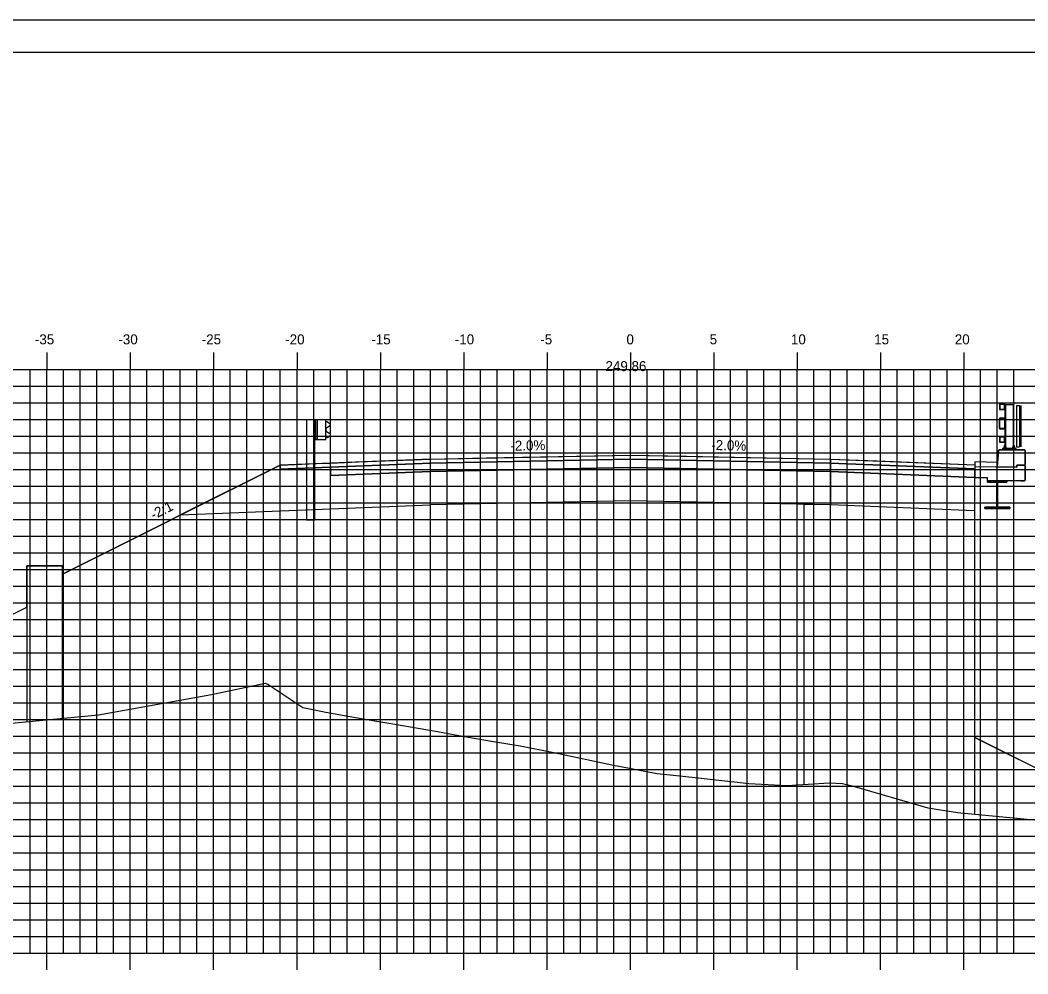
# Model space of a CAD drawing. Extents: x -22 to 1480, y -1511 to 8.
# Drawn here: x 816.8 to 877.3, y -1458.6 to -1401.4 of the extents above; entities that cross this region are included whole.
import ezdxf

# ---------------------------------------------------------------- set-up
doc = ezdxf.new("R2010")
doc.units = 0
for name, color, linetype in [('ANNOTATION', 7, 'Continuous'), ('BORDER', 7, 'Continuous'), ('D_Bridge_Deck', 7, 'Continuous'), ('D_Bridge_Railing', 7, 'Continuous'), ('D_Bridge_Superstructure', 7, 'Continuous'), ('D_Bridge_Superstructure_Slab', 7, 'Continuous'), ('D_Bridge_Wingwall', 7, 'Continuous'), ('D_Guardrail_Beam_Lt', 7, 'Continuous'), ('D_Roadway_Centerline', 7, 'Continuous'), ('D_Roadway_Centerline_Text', 7, 'Continuous'), ('D_Roadway_Edge_Shoulder', 7, 'Continuous'), ('D_Roadway_Edge_TW', 7, 'Continuous'), ('D_Roadway_Pavement', 7, 'Continuous'), ('D_Roadway_SlopeLines', 7, 'Continuous'), ('D_Roadway_SubGrade', 7, 'Continuous'), ('H_V ANNOTATION', 7, 'Continuous'), ('MAJOR', 7, 'Continuous'), ('MINOR', 7, 'Continuous'), ('PLOT BOUNDARY', 7, 'Continuous'), ('S_Roadway_Centerline', 7, 'Continuous')]:
    doc.layers.add(name, color=color, linetype=linetype)

msp = doc.modelspace()

# ---------------------------------------------------------------- linework, layer by layer
at = {"layer": 'BORDER'}
msp.add_line((938.426, -1403.331), (778.426, -1403.331), dxfattribs=at)
at = {"layer": 'D_Bridge_Deck'}
for p, q in [((876.593, -1428.203), (876.593, -1428.078)), ((876.593, -1428.078), (877.051, -1428.078))]:
    msp.add_line(p, q, dxfattribs=at)
for points in [[(877.051, -1428.078), (877.093, -1428.036), (877.093, -1427.2), (877.051, -1427.159), (875.551, -1427.159), (875.506, -1427.2), (875.426, -1428.18)], [(876.801, -1429.013), (876.092, -1429.013)]]:
    msp.add_lwpolyline(points, dxfattribs=at)
at = {"layer": 'D_Bridge_Railing'}
for p, q in [((875.551, -1424.45), (875.551, -1424.7)), ((875.572, -1424.45), (875.572, -1424.7)), ((875.843, -1424.409), (875.593, -1424.409)), ((875.843, -1424.43), (875.593, -1424.43)), ((875.863, -1424.7), (875.863, -1424.45)), ((875.884, -1424.7), (875.884, -1424.45)), ((875.922, -1424.45), (875.922, -1426.982)), ((876.378, -1424.45), (876.378, -1426.982)), ((876.582, -1424.492), (876.582, -1426.983)), ((876.582, -1424.492), (876.749, -1424.492)), ((876.749, -1424.492), (876.749, -1426.983)), ((875.593, -1424.721), (875.843, -1424.721)), ((875.593, -1424.742), (875.843, -1424.742)), ((875.551, -1425.857), (875.551, -1425.294)), ((875.577, -1425.857), (875.577, -1425.294)), ((875.603, -1425.242), (875.832, -1425.242)), ((875.603, -1425.268), (875.832, -1425.268)), ((875.858, -1425.294), (875.858, -1425.857)), ((875.884, -1425.294), (875.884, -1425.857)), ((875.832, -1425.883), (875.603, -1425.883)), ((875.832, -1425.909), (875.603, -1425.909)), ((875.551, -1426.409), (875.551, -1426.659)), ((875.572, -1426.409), (875.572, -1426.659)), ((875.843, -1426.367), (875.593, -1426.367)), ((875.843, -1426.388), (875.593, -1426.388)), ((875.593, -1426.68), (875.843, -1426.68)), ((875.593, -1426.7), (875.843, -1426.7)), ((875.921, -1426.909), (875.848, -1426.909)), ((875.921, -1426.917), (875.848, -1426.917)), ((875.921, -1426.925), (875.848, -1426.925)), ((875.921, -1426.933), (875.848, -1426.933)), ((875.863, -1426.659), (875.863, -1426.409)), ((875.903, -1426.913), (875.866, -1426.913)), ((875.903, -1426.921), (875.866, -1426.921)), ((875.903, -1426.929), (875.866, -1426.929)), ((875.903, -1426.938), (875.866, -1426.938)), ((875.884, -1426.659), (875.884, -1426.409)), ((876.452, -1426.909), (876.379, -1426.909)), ((876.452, -1426.917), (876.379, -1426.917)), ((876.452, -1426.925), (876.379, -1426.925)), ((876.452, -1426.933), (876.379, -1426.933)), ((876.434, -1426.913), (876.397, -1426.913)), ((876.434, -1426.921), (876.397, -1426.921)), ((876.434, -1426.929), (876.397, -1426.929)), ((876.434, -1426.938), (876.397, -1426.938)), ((875.921, -1426.942), (875.848, -1426.942)), ((875.921, -1426.95), (875.848, -1426.95)), ((875.921, -1426.958), (875.848, -1426.958)), ((875.921, -1426.967), (875.848, -1426.967)), ((875.921, -1426.975), (875.848, -1426.975)), ((875.85, -1426.99), (875.85, -1427.046)), ((875.903, -1426.946), (875.866, -1426.946)), ((875.903, -1426.954), (875.866, -1426.954)), ((875.903, -1426.962), (875.866, -1426.962)), ((875.903, -1426.971), (875.866, -1426.971)), ((875.903, -1426.979), (875.866, -1426.979)), ((875.919, -1426.99), (875.919, -1427.046)), ((876.452, -1426.942), (876.379, -1426.942)), ((876.452, -1426.95), (876.379, -1426.95)), ((876.452, -1426.958), (876.379, -1426.958)), ((876.452, -1426.967), (876.379, -1426.967)), ((876.452, -1426.975), (876.379, -1426.975)), ((876.381, -1426.99), (876.381, -1427.046)), ((876.434, -1426.946), (876.397, -1426.946)), ((876.434, -1426.954), (876.397, -1426.954)), ((876.434, -1426.962), (876.397, -1426.962)), ((876.434, -1426.971), (876.397, -1426.971)), ((876.434, -1426.979), (876.397, -1426.979)), ((876.45, -1426.99), (876.45, -1427.046)), ((876.582, -1426.983), (876.749, -1426.983))]:
    msp.add_line(p, q, dxfattribs=at)
for points in [[(876.416, -1426.9), (876.416, -1424.45), (875.884, -1424.45), (875.884, -1426.9)], [(876.832, -1424.492), (876.832, -1426.983)], [(875.921, -1426.982), (875.921, -1426.909), (875.912, -1426.9), (875.856, -1426.9), (875.848, -1426.909), (875.848, -1426.982)], [(876.452, -1426.982), (876.452, -1426.909), (876.444, -1426.9), (876.387, -1426.9), (876.379, -1426.909), (876.379, -1426.982)]]:
    msp.add_lwpolyline(points, dxfattribs=at)
for points in [[(876.56, -1427.067), (875.74, -1427.067), (875.74, -1427.149), (876.56, -1427.149)], [(876.56, -1427.149), (875.74, -1427.149), (875.74, -1427.159), (876.56, -1427.159)], [(875.957, -1427.067), (875.811, -1427.067), (875.811, -1427.054), (875.957, -1427.054)], [(875.953, -1426.99), (875.939, -1426.982), (875.829, -1426.982), (875.815, -1426.99), (875.815, -1427.046), (875.829, -1427.054), (875.939, -1427.054), (875.953, -1427.046)], [(876.488, -1427.067), (876.343, -1427.067), (876.343, -1427.054), (876.488, -1427.054)], [(876.484, -1426.99), (876.471, -1426.982), (876.36, -1426.982), (876.347, -1426.99), (876.347, -1427.046), (876.36, -1427.054), (876.471, -1427.054), (876.484, -1427.046)]]:
    msp.add_lwpolyline(points, close=True, dxfattribs=at)
for centre, radius, start, end in [((875.593, -1424.45), 0.0417, 90, 180), ((875.593, -1424.45), 0.0208, 90, 180), ((875.843, -1424.45), 0.0417, 360, 90), ((875.843, -1424.45), 0.0208, 360, 90), ((875.593, -1424.7), 0.0417, 180, 270), ((875.593, -1424.7), 0.0208, 180, 270), ((875.843, -1424.7), 0.0417, 270, 0), ((875.843, -1424.7), 0.0208, 270, 0), ((875.603, -1425.294), 0.052, 90, 180), ((875.603, -1425.294), 0.026, 90, 180), ((875.832, -1425.294), 0.052, 360, 90), ((875.832, -1425.294), 0.026, 360, 90), ((875.603, -1425.857), 0.052, 180, 270), ((875.603, -1425.857), 0.026, 180, 270), ((875.832, -1425.857), 0.052, 270, 0), ((875.832, -1425.857), 0.026, 270, 0), ((875.593, -1426.409), 0.0417, 90, 180), ((875.593, -1426.659), 0.0417, 180, 270), ((875.593, -1426.409), 0.0208, 90, 180), ((875.593, -1426.659), 0.0208, 180, 270), ((875.843, -1426.409), 0.0417, 360, 90), ((875.843, -1426.409), 0.0208, 360, 90), ((875.843, -1426.659), 0.0417, 270, 0), ((875.843, -1426.659), 0.0208, 270, 0), ((875.833, -1427.015), 0.0302, 55.4339, 120), ((875.833, -1427.021), 0.0302, 240, 304.5661), ((875.884, -1427.099), 0.114, 72.41205, 107.58795), ((875.884, -1426.937), 0.114, 252.41205, 287.58795), ((875.936, -1427.015), 0.0302, 60, 124.5661), ((875.936, -1427.021), 0.0302, 235.4339, 300), ((876.364, -1427.015), 0.0302, 55.4339, 120), ((876.364, -1427.021), 0.0302, 240, 304.5661), ((876.416, -1427.099), 0.114, 72.41205, 107.58795), ((876.416, -1426.937), 0.114, 252.41205, 287.58795), ((876.467, -1427.015), 0.0302, 60, 124.5661), ((876.467, -1427.021), 0.0302, 235.4339, 300)]:
    msp.add_arc(centre, radius, start, end, dxfattribs=at)
at = {"layer": 'D_Bridge_Superstructure'}
for p, q in [((876.009, -1429.013), (874.842, -1429.013)), ((874.842, -1429.013), (874.842, -1429.096)), ((875.447, -1429.096), (875.405, -1429.096)), ((875.447, -1429.096), (875.405, -1429.096)), ((875.447, -1429.096), (876.009, -1429.096)), ((876.009, -1429.096), (876.009, -1429.013)), ((875.405, -1430.596), (874.676, -1430.596)), ((874.676, -1430.596), (874.676, -1430.68)), ((875.405, -1430.596), (874.676, -1430.596)), ((875.447, -1430.596), (875.405, -1430.596)), ((875.447, -1430.596), (875.405, -1430.596))]:
    msp.add_line(p, q, dxfattribs=at)
for points in [[(874.842, -1429.013), (876.009, -1429.013), (876.009, -1429.096), (874.842, -1429.096)], [(875.405, -1429.096), (875.447, -1429.096), (875.447, -1430.596), (875.405, -1430.596)], [(874.676, -1430.596), (876.176, -1430.596), (876.176, -1430.68), (874.676, -1430.68)]]:
    msp.add_lwpolyline(points, close=True, dxfattribs=at)
for points in [[(875.447, -1429.096), (876.009, -1429.096), (876.009, -1429.013), (874.842, -1429.013), (874.842, -1429.096), (875.405, -1429.096), (875.447, -1429.096)], [(874.842, -1429.096), (875.405, -1429.096), (875.447, -1429.096)], [(875.405, -1429.096), (875.405, -1430.596), (875.447, -1430.596), (875.447, -1429.096)], [(875.405, -1429.096), (875.405, -1430.596), (875.447, -1430.596), (875.447, -1429.096)], [(874.676, -1430.596), (874.676, -1430.68), (876.176, -1430.68), (876.176, -1430.596), (875.447, -1430.596)], [(874.676, -1430.68), (876.176, -1430.68), (876.176, -1430.596), (875.447, -1430.596)]]:
    msp.add_lwpolyline(points, dxfattribs=at)
at = {"layer": 'D_Bridge_Superstructure_Slab'}
msp.add_line((874.083, -1427.882), (874.083, -1428.805), dxfattribs=at)
msp.add_lwpolyline([(875.426, -1428.18), (875.506, -1427.2), (875.551, -1427.159), (877.051, -1427.159), (877.093, -1427.2), (877.093, -1428.036), (877.051, -1428.078), (876.593, -1428.078), (876.593, -1428.203)], close=True, dxfattribs=at)
for points in [[(874.083, -1428.153), (875.426, -1428.18), (875.448, -1427.909), (874.083, -1427.882)], [(874.083, -1428.153), (876.593, -1428.203), (876.593, -1428.078), (877.051, -1428.078), (877.093, -1428.12), (877.093, -1428.971), (877.051, -1429.013), (876.843, -1429.013), (876.843, -1428.971), (876.801, -1429.013), (874.842, -1429.013), (874.842, -1428.835), (874.083, -1428.819)], [(876.843, -1429.013), (877.051, -1429.013), (877.093, -1428.971), (877.093, -1428.12), (877.051, -1428.078)], [(874.083, -1428.153), (876.593, -1428.203)], [(874.083, -1428.819), (874.842, -1428.835)], [(876.092, -1429.013), (874.842, -1429.013), (874.842, -1428.835)], [(876.843, -1429.013), (876.843, -1428.971), (876.801, -1429.013)], [(876.843, -1429.013), (876.843, -1428.971), (876.801, -1429.013)]]:
    msp.add_lwpolyline(points, dxfattribs=at)
at = {"layer": 'D_Bridge_Wingwall'}
for points in [[(874.083, -1448.999), (874.083, -1430.805), (865.426, -1430.459), (863.817, -1430.427), (863.817, -1447.222)], [(819.36, -1443.26), (819.36, -1434.102), (817.217, -1434.102), (817.217, -1434.102), (817.217, -1443.464)]]:
    msp.add_lwpolyline(points, dxfattribs=at)
at = {"layer": 'D_Guardrail_Beam_Lt'}
for p, q in [((833.997, -1425.365), (833.997, -1431.365)), ((834.468, -1425.365), (833.997, -1425.365)), ((835.155, -1425.365), (834.468, -1425.365)), ((834.468, -1425.365), (834.468, -1426.532)), ((834.53, -1425.365), (834.53, -1426.532)), ((834.634, -1425.365), (834.634, -1426.532)), ((835.155, -1426.532), (835.155, -1425.365)), ((835.155, -1425.449), (835.229, -1425.463)), ((835.389, -1425.713), (835.193, -1425.849)), ((835.245, -1425.47), (835.389, -1425.57)), ((835.16, -1425.914), (835.16, -1425.984)), ((835.193, -1426.048), (835.389, -1426.184)), ((835.389, -1426.327), (835.245, -1426.427)), ((834.468, -1426.532), (835.155, -1426.532)), ((834.489, -1431.365), (834.489, -1426.532)), ((835.229, -1426.434), (835.155, -1426.449)), ((834.489, -1431.365), (833.997, -1431.365))]:
    msp.add_line(p, q, dxfattribs=at)
for centre, major_axis, start_param, end_param in [((835.221, -1425.504), (0.0417, 0), 0.959931, 1.376053), ((835.338, -1425.642), (0.0877, 0), 5.323254, 7.243116), ((835.239, -1425.914), (-0.0789, 0), 5.323254, 6.283185), ((835.239, -1425.984), (-0.0789, 0), 6.283185, 7.243116), ((835.338, -1426.256), (0.0877, 0), 5.323254, 7.243116), ((835.221, -1426.393), (0.0417, 0), 4.907132, 5.323254)]:
    msp.add_ellipse(centre, major_axis=major_axis, ratio=0.995501, start_param=start_param, end_param=end_param, dxfattribs=at)
at = {"layer": 'D_Roadway_Centerline'}
for points in [[(800.861, -1444.759), (817.217, -1436.581), (817.217, -1434.102), (819.36, -1434.102), (819.36, -1434.602), (832.426, -1428.069), (834.586, -1427.982), (835.426, -1427.949), (837.106, -1427.882), (841.426, -1427.709), (844.786, -1427.642), (853.426, -1427.469), (856.786, -1427.536), (865.426, -1427.709), (868.226, -1427.821), (874.083, -1428.055)], [(874.083, -1444.402), (879.451, -1447.086), (880.06, -1447.196), (885.062, -1448.098), (889.433, -1448.888), (890.33, -1449.05), (891.456, -1449.252), (900.867, -1448.972)]]:
    msp.add_lwpolyline(points, dxfattribs=at)
at = {"layer": 'D_Roadway_Edge_Shoulder'}
msp.add_lwpolyline([(841.426, -1427.709), (835.426, -1427.949), (835.426, -1427.949), (832.426, -1428.069), (832.426, -1428.319), (835.426, -1428.199), (835.426, -1428.199), (841.426, -1427.959)], close=True, dxfattribs=at)
msp.add_lwpolyline([(874.083, -1428.305), (865.426, -1427.959), (865.426, -1427.709), (874.083, -1428.055)], dxfattribs=at)
at = {"layer": 'D_Roadway_Edge_TW'}
msp.add_lwpolyline([(841.426, -1427.959), (841.426, -1427.709), (853.426, -1427.469), (865.426, -1427.709), (865.426, -1427.959), (853.426, -1427.719)], close=True, dxfattribs=at)
at = {"layer": 'D_Roadway_Pavement'}
for points in [[(841.426, -1427.959), (835.426, -1428.199), (835.426, -1428.199), (835.426, -1428.699), (841.426, -1428.459), (841.426, -1427.959)], [(865.426, -1427.959), (874.083, -1428.305)], [(874.083, -1428.805), (865.426, -1428.459), (865.426, -1427.959)]]:
    msp.add_lwpolyline(points, dxfattribs=at)
msp.add_lwpolyline([(841.426, -1428.459), (841.426, -1427.959), (853.426, -1427.719), (865.426, -1427.959), (865.426, -1428.459), (853.426, -1428.219)], close=True, dxfattribs=at)
at = {"layer": 'D_Roadway_SlopeLines'}
msp.add_line((879.451, -1447.086), (874.083, -1444.402), dxfattribs=at)
msp.add_lwpolyline([(832.426, -1428.069), (819.36, -1434.602)], dxfattribs=at)
at = {"layer": 'D_Roadway_SubGrade'}
for p, q in [((874.083, -1428.805), (874.083, -1428.305)), ((874.083, -1430.805), (874.083, -1428.819))]:
    msp.add_line(p, q, dxfattribs=at)
for points in [[(841.426, -1428.459), (835.426, -1428.699), (835.426, -1428.199), (832.426, -1428.319), (832.426, -1428.069), (826.448, -1431.058), (841.426, -1430.459)], [(841.426, -1430.459), (841.426, -1428.459), (853.426, -1428.219), (865.426, -1428.459), (865.426, -1430.459), (853.426, -1430.219)]]:
    msp.add_lwpolyline(points, close=True, dxfattribs=at)
msp.add_lwpolyline([(874.083, -1430.805), (865.426, -1430.459), (865.426, -1428.459), (874.083, -1428.805)], dxfattribs=at)
at = {"layer": 'MAJOR'}
for p, q in [((818.426, -1421.329), (818.426, -1422.331)), ((823.426, -1421.329), (823.426, -1422.331)), ((828.426, -1421.329), (828.426, -1422.331)), ((833.426, -1421.329), (833.426, -1422.331)), ((838.426, -1421.329), (838.426, -1422.331)), ((843.426, -1421.329), (843.426, -1422.331)), ((848.426, -1421.329), (848.426, -1422.331)), ((853.426, -1421.329), (853.426, -1422.331)), ((858.426, -1421.329), (858.426, -1422.331)), ((863.426, -1421.329), (863.426, -1422.331)), ((868.426, -1421.329), (868.426, -1422.331)), ((873.426, -1421.329), (873.426, -1422.331)), ((783.426, -1422.331), (923.426, -1422.331)), ((783.426, -1422.331), (923.426, -1422.331)), ((818.426, -1457.331), (818.426, -1422.331)), ((823.426, -1457.331), (823.426, -1422.331)), ((828.426, -1457.331), (828.426, -1422.331)), ((833.426, -1457.331), (833.426, -1422.331)), ((838.426, -1457.331), (838.426, -1422.331)), ((843.426, -1457.331), (843.426, -1422.331)), ((848.426, -1457.331), (848.426, -1422.331)), ((853.426, -1457.331), (853.426, -1422.331)), ((858.426, -1457.331), (858.426, -1422.331)), ((863.426, -1457.331), (863.426, -1422.331)), ((868.426, -1457.331), (868.426, -1422.331)), ((873.426, -1457.331), (873.426, -1422.331)), ((783.426, -1427.331), (923.426, -1427.331)), ((783.426, -1432.331), (923.426, -1432.331)), ((783.426, -1437.331), (923.426, -1437.331)), ((783.426, -1442.331), (923.426, -1442.331)), ((783.426, -1447.331), (923.426, -1447.331)), ((783.426, -1452.331), (923.426, -1452.331)), ((783.426, -1457.331), (923.426, -1457.331)), ((783.426, -1457.331), (923.426, -1457.331)), ((818.426, -1458.333), (818.426, -1457.331)), ((823.426, -1458.333), (823.426, -1457.331)), ((828.426, -1458.333), (828.426, -1457.331)), ((833.426, -1458.333), (833.426, -1457.331)), ((838.426, -1458.333), (838.426, -1457.331)), ((843.426, -1458.333), (843.426, -1457.331)), ((848.426, -1458.333), (848.426, -1457.331)), ((853.426, -1458.333), (853.426, -1457.331)), ((858.426, -1458.333), (858.426, -1457.331)), ((863.426, -1458.333), (863.426, -1457.331)), ((868.426, -1458.333), (868.426, -1457.331)), ((873.426, -1458.333), (873.426, -1457.331))]:
    msp.add_line(p, q, dxfattribs=at)
at = {"layer": 'MINOR'}
for p, q in [((817.426, -1457.331), (817.426, -1422.331)), ((819.426, -1457.331), (819.426, -1422.331)), ((820.426, -1457.331), (820.426, -1422.331)), ((821.426, -1457.331), (821.426, -1422.331)), ((822.426, -1457.331), (822.426, -1422.331)), ((824.426, -1457.331), (824.426, -1422.331)), ((825.426, -1457.331), (825.426, -1422.331)), ((826.426, -1457.331), (826.426, -1422.331)), ((827.426, -1457.331), (827.426, -1422.331)), ((829.426, -1457.331), (829.426, -1422.331)), ((830.426, -1457.331), (830.426, -1422.331)), ((831.426, -1457.331), (831.426, -1422.331)), ((832.426, -1457.331), (832.426, -1422.331)), ((834.426, -1457.331), (834.426, -1422.331)), ((835.426, -1457.331), (835.426, -1422.331)), ((836.426, -1457.331), (836.426, -1422.331)), ((837.426, -1457.331), (837.426, -1422.331)), ((839.426, -1457.331), (839.426, -1422.331)), ((840.426, -1457.331), (840.426, -1422.331)), ((841.426, -1457.331), (841.426, -1422.331)), ((842.426, -1457.331), (842.426, -1422.331)), ((844.426, -1457.331), (844.426, -1422.331)), ((845.426, -1457.331), (845.426, -1422.331)), ((846.426, -1457.331), (846.426, -1422.331)), ((847.426, -1457.331), (847.426, -1422.331)), ((849.426, -1457.331), (849.426, -1422.331)), ((850.426, -1457.331), (850.426, -1422.331)), ((851.426, -1457.331), (851.426, -1422.331)), ((852.426, -1457.331), (852.426, -1422.331)), ((854.426, -1457.331), (854.426, -1422.331)), ((855.426, -1457.331), (855.426, -1422.331)), ((856.426, -1457.331), (856.426, -1422.331)), ((857.426, -1457.331), (857.426, -1422.331)), ((859.426, -1457.331), (859.426, -1422.331)), ((860.426, -1457.331), (860.426, -1422.331)), ((861.426, -1457.331), (861.426, -1422.331)), ((862.426, -1457.331), (862.426, -1422.331)), ((864.426, -1457.331), (864.426, -1422.331)), ((865.426, -1457.331), (865.426, -1422.331)), ((866.426, -1457.331), (866.426, -1422.331)), ((867.426, -1457.331), (867.426, -1422.331)), ((869.426, -1457.331), (869.426, -1422.331)), ((870.426, -1457.331), (870.426, -1422.331)), ((871.426, -1457.331), (871.426, -1422.331)), ((872.426, -1457.331), (872.426, -1422.331)), ((874.426, -1457.331), (874.426, -1422.331)), ((875.426, -1457.331), (875.426, -1422.331)), ((876.426, -1457.331), (876.426, -1422.331)), ((783.426, -1423.331), (923.426, -1423.331)), ((783.426, -1424.331), (923.426, -1424.331)), ((783.426, -1425.331), (923.426, -1425.331)), ((783.426, -1426.331), (923.426, -1426.331)), ((783.426, -1428.331), (923.426, -1428.331)), ((783.426, -1429.331), (923.426, -1429.331)), ((783.426, -1430.331), (923.426, -1430.331)), ((783.426, -1431.331), (923.426, -1431.331)), ((783.426, -1433.331), (923.426, -1433.331)), ((783.426, -1434.331), (923.426, -1434.331)), ((783.426, -1435.331), (923.426, -1435.331)), ((783.426, -1436.331), (923.426, -1436.331)), ((783.426, -1438.331), (923.426, -1438.331)), ((783.426, -1439.331), (923.426, -1439.331)), ((783.426, -1440.331), (923.426, -1440.331)), ((783.426, -1441.331), (923.426, -1441.331)), ((783.426, -1443.331), (923.426, -1443.331)), ((783.426, -1444.331), (923.426, -1444.331)), ((783.426, -1445.331), (923.426, -1445.331)), ((783.426, -1446.331), (923.426, -1446.331)), ((783.426, -1448.331), (923.426, -1448.331)), ((783.426, -1449.331), (923.426, -1449.331)), ((783.426, -1450.331), (923.426, -1450.331)), ((783.426, -1451.331), (923.426, -1451.331)), ((783.426, -1453.331), (923.426, -1453.331)), ((783.426, -1454.331), (923.426, -1454.331)), ((783.426, -1455.331), (923.426, -1455.331)), ((783.426, -1456.331), (923.426, -1456.331))]:
    msp.add_line(p, q, dxfattribs=at)
at = {"layer": 'PLOT BOUNDARY'}
msp.add_lwpolyline([(770.333, -1511.39), (940.333, -1511.39), (940.333, -1401.39), (770.333, -1401.39)], close=True, dxfattribs=at)
at = {"layer": 'S_Roadway_Centerline'}
msp.add_lwpolyline([(803.789, -1444.743), (821.514, -1443.055), (828.303, -1441.819), (831.525, -1441.145), (831.681, -1441.216), (833.779, -1442.616), (835.146, -1442.893), (837.267, -1443.269), (838.457, -1443.466), (840.118, -1443.745), (841.86, -1444.044), (843.136, -1444.279), (845.212, -1444.64), (846.818, -1444.904), (848.839, -1445.298), (852.41, -1446.058), (853.367, -1446.253), (855.011, -1446.557), (855.812, -1446.642), (857.304, -1446.809), (859.261, -1447.019), (859.672, -1447.069), (860.527, -1447.161), (862.834, -1447.283), (865.35, -1447.126), (866.138, -1447.172), (866.719, -1447.294), (871.253, -1448.623), (873.038, -1448.9), (877.633, -1449.335)], dxfattribs=at)
msp.add_lwpolyline([(803.789, -1444.743), (821.514, -1443.055), (828.303, -1441.819), (831.525, -1441.145), (831.681, -1441.216), (833.779, -1442.616), (835.146, -1442.893), (837.267, -1443.269), (838.457, -1443.466), (840.118, -1443.745), (841.86, -1444.044), (843.136, -1444.279), (845.212, -1444.64), (846.818, -1444.904), (848.839, -1445.298), (852.41, -1446.058), (853.367, -1446.253), (855.011, -1446.557), (855.812, -1446.642), (857.304, -1446.809), (859.261, -1447.019), (859.672, -1447.069), (860.527, -1447.161), (862.834, -1447.283), (865.35, -1447.126), (866.138, -1447.172), (866.719, -1447.294), (871.253, -1448.623), (873.038, -1448.9), (877.633, -1449.335)], dxfattribs=at)

# ---------------------------------------------------------------- texts
at = {"layer": 'ANNOTATION'}
for s, rotation, p in [('-2.0%', 1.14576, (846.229, -1427.212)), ('-2.0%', 358.85424, (858.269, -1427.165)), ('-2:1', 26.56505, (824.822, -1431.353))]:
    msp.add_text(s, height=0.6, rotation=rotation, dxfattribs=at).set_placement(p)
at = {"layer": 'D_Roadway_Centerline'}
for s, p in [('C', (853.421, -1427.469)), ('L', (853.426, -1427.476))]:
    msp.add_text(s, height=0.0146, dxfattribs=at).set_placement(p)
at = {"layer": 'D_Roadway_Centerline_Text'}
msp.add_text('249.86', height=0.6, dxfattribs=at).set_placement((851.928, -1422.437))
at = {"layer": 'H_V ANNOTATION'}
for s, p in [('-35', (817.706, -1420.831)), ('-30', (822.714, -1420.831)), ('-25', (827.712, -1420.831)), ('-20', (832.72, -1420.831)), ('-15', (837.883, -1420.831)), ('-10', (842.891, -1420.831)), ('-5', (848.017, -1420.831)), ('0', (853.185, -1420.831)), ('5', (858.177, -1420.831)), ('10', (863.051, -1420.831)), ('15', (868.043, -1420.831)), ('20', (872.88, -1420.831))]:
    msp.add_text(s, height=0.6, dxfattribs=at).set_placement(p)

doc.saveas('drawing.dxf')
